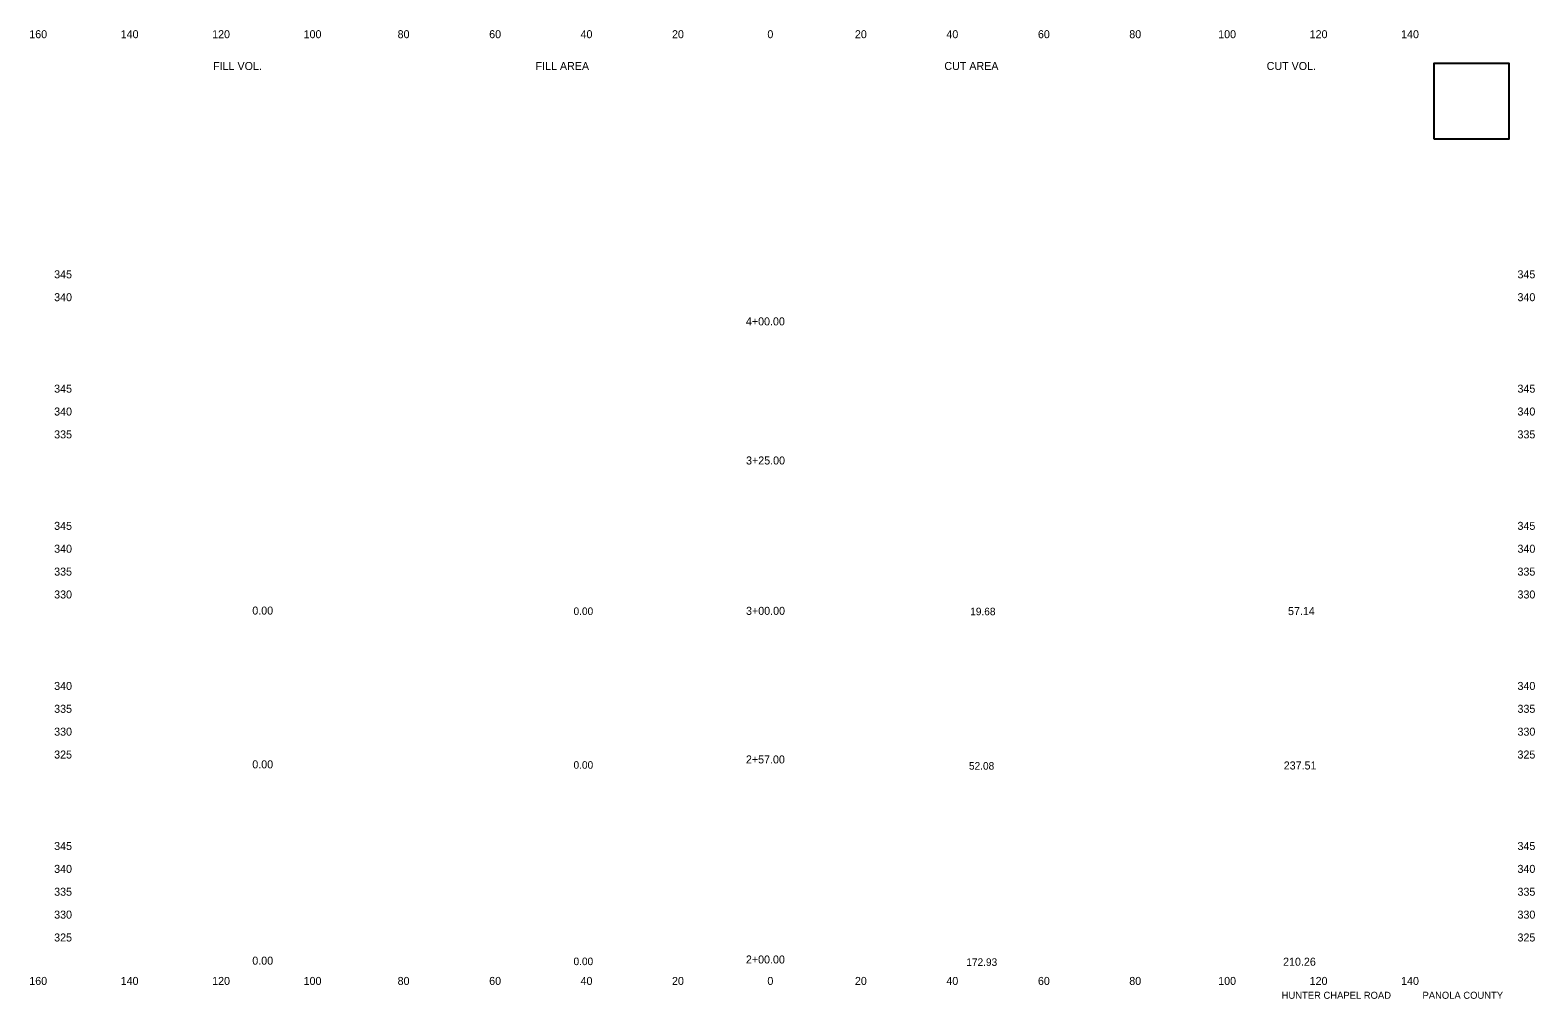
# Model space of a CAD drawing. Extents: x 21481 to 21810, y 6472 to 6914.
# Drawn here: x 21480.9 to 21809.9, y 6702.3 to 6914.1 of the extents above; entities that cross this region are included whole.
import ezdxf

# ---------------------------------------------------------------- set-up
doc = ezdxf.new("R2010")
doc.units = 0
for name, color, linetype in [('ALI_DESIGN_SECONDARY_STA', 7, 'Continuous'), ('SHEET_CONSULTANT_STAMP', 7, 'Continuous'), ('XS_SHEET_EW_TX_AREA', 7, 'Continuous'), ('XS_SHEET_EW_TX_VOLUME', 7, 'Continuous'), ('XS_SHEET_LABELS_ELEVATION', 7, 'Continuous'), ('XS_SHEET_LABELS_OFFSET', 7, 'Continuous'), ('XS_SHEET_LABELS_STATION', 7, 'Continuous'), ('XS_SHEET_TX', 7, 'Continuous')]:
    doc.layers.add(name, color=color, linetype=linetype)

msp = doc.modelspace()

# ---------------------------------------------------------------- linework, layer by layer
at = {"layer": 'SHEET_CONSULTANT_STAMP'}
msp.add_lwpolyline([(21787.84, 6890.34), (21804.34, 6890.34), (21804.34, 6906.84), (21787.84, 6906.84)], close=True, dxfattribs=at)

# ---------------------------------------------------------------- texts
at = {"layer": 'ALI_DESIGN_SECONDARY_STA'}
for s, p in [('HUNTER CHAPEL ROAD ', (21754.57, 6702.31)), ('PANOLA COUNTY', (21785.37, 6702.31))]:
    msp.add_text(s, height=1.54, dxfattribs=at).set_placement(p)
at = {"layer": 'XS_SHEET_EW_TX_AREA'}
for s, p in [('0.00', (21599.72, 6786.23)), ('19.68', (21686.47, 6786.17)), ('0.00', (21599.72, 6752.61)), ('52.08', (21686.19, 6752.41)), ('0.00', (21599.72, 6709.67)), ('172.93', (21685.62, 6709.5))]:
    msp.add_text(s, height=1.65, dxfattribs=at).set_placement(p)
at = {"layer": 'XS_SHEET_EW_TX_VOLUME'}
for s, p in [('0.00', (21529.47, 6786.32)), ('57.14', (21755.96, 6786.21)), ('0.00', (21529.47, 6752.7)), ('237.51', (21755.02, 6752.45)), ('0.00', (21529.47, 6709.77)), ('210.26', (21754.88, 6709.54))]:
    msp.add_text(s, height=1.75, dxfattribs=at).set_placement(p)
at = {"layer": 'XS_SHEET_LABELS_ELEVATION'}
for s, p in [('  345  ', (21484.84, 6859.84)), ('  345  ', (21804.84, 6859.84)), ('  340  ', (21484.84, 6854.84)), ('  340  ', (21804.84, 6854.84)), ('  345  ', (21484.84, 6834.84)), ('  345  ', (21804.84, 6834.84)), ('  340  ', (21484.84, 6829.84)), ('  340  ', (21804.84, 6829.84)), ('  335  ', (21484.84, 6824.84)), ('  335  ', (21804.84, 6824.84)), ('  345  ', (21484.84, 6804.84)), ('  345  ', (21804.84, 6804.84)), ('  340  ', (21484.84, 6799.84)), ('  340  ', (21804.84, 6799.84)), ('  335  ', (21484.84, 6794.84)), ('  335  ', (21804.84, 6794.84)), ('  330  ', (21484.84, 6789.84)), ('  330  ', (21804.84, 6789.84)), ('  340  ', (21484.84, 6769.84)), ('  340  ', (21804.84, 6769.84)), ('  335  ', (21484.84, 6764.84)), ('  335  ', (21804.84, 6764.84)), ('  330  ', (21484.84, 6759.84)), ('  330  ', (21804.84, 6759.84)), ('  325  ', (21484.84, 6754.84)), ('  325  ', (21804.84, 6754.84)), ('  345  ', (21484.84, 6734.84)), ('  345  ', (21804.84, 6734.84)), ('  340  ', (21484.84, 6729.84)), ('  340  ', (21804.84, 6729.84)), ('  335  ', (21484.84, 6724.84)), ('  335  ', (21804.84, 6724.84)), ('  330  ', (21484.84, 6719.84)), ('  330  ', (21804.84, 6719.84)), ('  325  ', (21484.84, 6714.84)), ('  325  ', (21804.84, 6714.84))]:
    msp.add_text(s, height=1.75, dxfattribs=at).set_placement(p)
at = {"layer": 'XS_SHEET_LABELS_OFFSET'}
for s, p in [('  160  ', (21479.4, 6912.34)), ('  140  ', (21499.39, 6912.34)), ('  120  ', (21519.39, 6912.34)), ('  100  ', (21539.39, 6912.34)), ('  80  ', (21559.95, 6912.34)), ('  60  ', (21579.97, 6912.34)), ('  40  ', (21599.95, 6912.34)), ('  20  ', (21619.95, 6912.34)), ('  0  ', (21640.81, 6912.34)), ('  0  ', (21640.81, 6912.34)), ('  20  ', (21659.95, 6912.34)), ('  40  ', (21679.95, 6912.34)), ('  60  ', (21699.97, 6912.34)), ('  80  ', (21719.95, 6912.34)), ('  100  ', (21739.39, 6912.34)), ('  120  ', (21759.39, 6912.34)), ('  140  ', (21779.39, 6912.34)), ('  160  ', (21479.4, 6705.34)), ('  140  ', (21499.39, 6705.34)), ('  120  ', (21519.39, 6705.34)), ('  100  ', (21539.39, 6705.34)), ('  80  ', (21559.95, 6705.34)), ('  60  ', (21579.97, 6705.34)), ('  40  ', (21599.95, 6705.34)), ('  20  ', (21619.95, 6705.34)), ('  0  ', (21640.81, 6705.34)), ('  0  ', (21640.81, 6705.34)), ('  20  ', (21659.95, 6705.34)), ('  40  ', (21679.95, 6705.34)), ('  60  ', (21699.97, 6705.34)), ('  80  ', (21719.95, 6705.34)), ('  100  ', (21739.39, 6705.34)), ('  120  ', (21759.39, 6705.34)), ('  140  ', (21779.39, 6705.34))]:
    msp.add_text(s, height=1.75, dxfattribs=at).set_placement(p)
at = {"layer": 'XS_SHEET_LABELS_STATION'}
for s, p in [('  4+00.00  ', (21636.11, 6849.55)), ('  3+25.00  ', (21636.14, 6819.14)), ('  3+00.00  ', (21636.14, 6786.26)), ('  2+57.00  ', (21636.11, 6753.77)), ('  2+00.00  ', (21636.11, 6710.03))]:
    msp.add_text(s, height=1.75, dxfattribs=at).set_placement(p)
at = {"layer": 'XS_SHEET_TX'}
for s, p in [('FILL VOL.', (21520.9, 6905.39)), ('FILL AREA', (21591.41, 6905.39)), ('CUT AREA', (21680.81, 6905.39)), ('CUT VOL.', (21751.29, 6905.39))]:
    msp.add_text(s, height=1.75, dxfattribs=at).set_placement(p)

doc.saveas('drawing.dxf')
